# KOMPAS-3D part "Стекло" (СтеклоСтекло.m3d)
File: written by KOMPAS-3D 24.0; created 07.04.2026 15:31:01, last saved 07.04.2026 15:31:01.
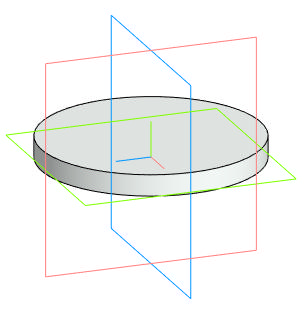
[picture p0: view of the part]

Document properties: Автор: Main; Полное имя файла: D:\DN.ru Аутсерс\Стекло смотровое DN.ru\Исходники\Стекло смотровое DN.ru SG2-34G-F тип В ГОСТ 21836-2021 Ду20 Ру40, углеродистая сталь, фланцевое\СтеклоСтекло.m3d

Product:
- Body: Твердое тело1  | qty 1
- Part/product: Стекло

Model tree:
1. Твердое тело1  (labels: Твердое тело1)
